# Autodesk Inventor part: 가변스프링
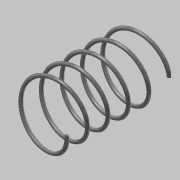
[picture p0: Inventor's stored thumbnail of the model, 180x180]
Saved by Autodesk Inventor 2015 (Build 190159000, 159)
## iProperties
Created: 2023-04
Part Number: 가변스프링
Material: 스테인레스 스틸
Document SubType Name: Modeling
Designer: SCD-A08
Density: 8 g/cm^3
Appearance: 반연마
Author: SCD-A08
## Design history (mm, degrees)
sketch "스케치4"
  geometry: L1 (0, 0)-(16, 0); L2 (16, 0)-(16, -58.5); L3 (16, -58.5)-(0, -58.5); L4 (0, -58.5)-(0, 0); C1 r 1 at (16, 0)
  constraints: 8 end point, 2 parallel, 1 centre point, 1 coincident, 1 horizontal, 1 perpendicular
  dimensions: "d15" = 58.5 distance of L1.end L2.end (derived); "d16" = 32 diameter of L2 L4; "d17" = 2 diameter of C1
feature "코일2" sketch "스케치4" pitch "d18" = 10; turns "d20" = 5; dims "d19" = 58.5 (= d15), "d21" = 0, angle "d22" = 90 deg, angle "d23" = 90 deg, "d24" = 0, "d25" = 0
node "작업 평면3"
node "작업 평면4"
sketch "스케치5"
  geometry: L1 (-15, 0)-(-17, 0) reference; 1 further point
  constraints: 1 horizontal alignment
extrude "돌출3" cut sketch "스케치5" distance "d26" = 10; taper "d27" = 0 deg
sketch "스케치6"
  geometry: L1 (-17, 0)-(-15, 0) reference; 1 further point
  constraints: 1 horizontal alignment
extrude "돌출4" cut sketch "스케치6" distance "d28" = 10; taper "d29" = 0 deg
node "솔리드2"
node "절단 모서리 투영3"
node "절단 모서리 투영4"
